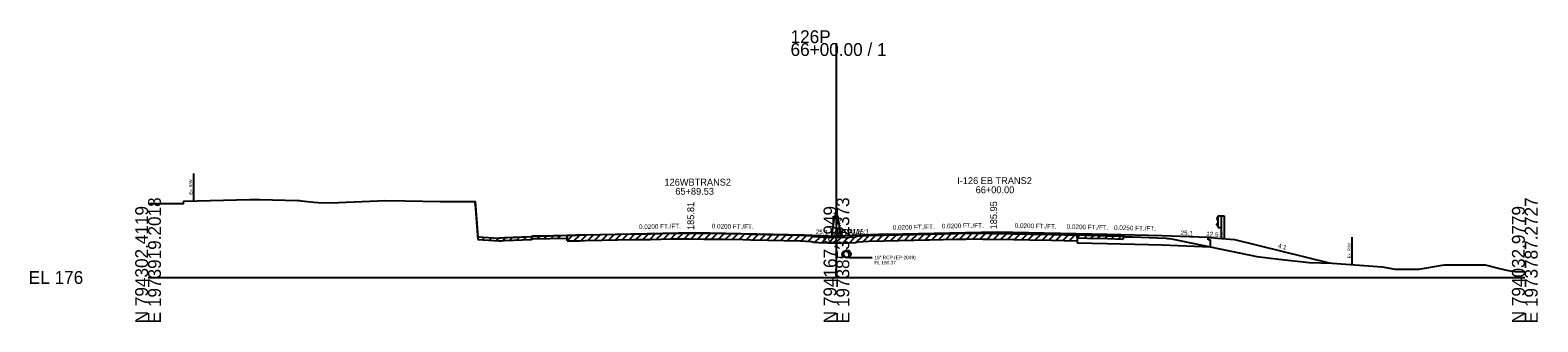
# Model space of a CAD drawing. Extents: x -161 to 1970889, y -4362 to 797231.
# Drawn here: x 2974.3 to 3302.8, y 1490.3 to 1554 of the extents above; entities that cross this region are included whole.
import ezdxf

# ---------------------------------------------------------------- set-up
doc = ezdxf.new("R2010")
doc.units = 0
for name, color, linetype in [('Default', 7, 'Continuous'), ('RD_GPK_XS_Cell', 7, 'Continuous'), ('RD_XS_Base', 7, 'Continuous'), ('RD_XS_EarthShd', 7, 'Continuous'), ('RD_XS_ExGround', 7, 'Continuous'), ('RD_XS_ExPaveRet', 7, 'Continuous'), ('RD_XS_ExRW', 7, 'Continuous'), ('RD_XS_GR', 7, 'Continuous'), ('RD_XS_MedBWall', 7, 'Continuous'), ('RD_XS_Misc_Line', 7, 'Continuous'), ('RD_XS_Pave', 7, 'Continuous'), ('RD_XS_PaveOvlay', 7, 'Continuous'), ('RD_XS_PaveShd', 7, 'Continuous'), ('RD_XS_Pipe', 7, 'Continuous'), ('RD_XS_TieSlope', 7, 'Continuous'), ('RD_XS_TX_Elev_EX', 7, 'Continuous'), ('RD_XS_TX_Elev_PR', 7, 'Continuous'), ('RD_XS_TX_MkPT', 7, 'Continuous'), ('RD_XS_TX_Profile', 7, 'Continuous'), ('RD_XS_TX_ShdSlope', 7, 'Continuous'), ('RD_XS_TX_Slope', 7, 'Continuous'), ('RD_XS_TX_Station', 7, 'Continuous')]:
    doc.layers.add(name, color=color, linetype=linetype)

msp = doc.modelspace()

# ---------------------------------------------------------------- linework, layer by layer
at = {"layer": 'RD_GPK_XS_Cell'}
for p, q in [((3150, 1500), (3150, 1551.16)), ((3000, 1500), (3150, 1500)), ((3150, 1500), (3300, 1500))]:
    msp.add_line(p, q, dxfattribs=at)
at = {"layer": 'RD_XS_Base'}
for p, q in [((3231.01, 1508.21), (3231.01, 1508.77)), ((3231.51, 1508.19), (3231.01, 1508.21)), ((3231.51, 1506.71), (3231.51, 1508.19)), ((3202.45, 1507.56), (3209, 1507.43)), ((3209, 1507.43), (3221, 1507.13)), ((3221, 1507.13), (3231.51, 1506.71))]:
    msp.add_line(p, q, dxfattribs=at)
at = {"layer": 'RD_XS_EarthShd'}
msp.add_line((3231.01, 1508.77), (3233.01, 1508.61), dxfattribs=at)
at = {"layer": 'RD_XS_ExGround'}
msp.add_lwpolyline([(3000, 1516.13), (3007.72, 1516.18), (3007.82, 1516.68), (3022.15, 1517), (3024.46, 1517.05), (3032.57, 1516.79), (3033.02, 1516.78), (3033.44, 1516.74), (3036.14, 1516.42), (3037.09, 1516.38), (3039.72, 1516.28), (3050.08, 1516.75), (3051.47, 1516.82), (3055.99, 1516.75), (3063.67, 1516.56), (3069.87, 1516.59), (3070.29, 1516.59), (3071.31, 1516.59), (3071.89, 1508.89), (3073.05, 1508.82), (3076.52, 1508.59), (3076.99, 1508.64), (3077.67, 1508.7), (3083.51, 1508.94), (3083.82, 1509.07), (3092.87, 1509.25), (3094.08, 1509.27), (3095.22, 1509.29), (3105.92, 1509.51), (3109.47, 1509.56), (3114.02, 1509.66), (3116.3, 1509.7), (3118.01, 1509.71), (3121.11, 1509.65), (3121.92, 1509.64), (3125.54, 1509.58), (3129.69, 1509.51), (3131.34, 1509.47), (3142.14, 1509.23), (3143.3, 1509.18), (3144.55, 1509.11), (3145.05, 1508.94), (3146.07, 1508.9), (3148.18, 1508.82), (3149.57, 1508.8), (3150, 1508.79), (3151.09, 1508.76), (3152.69, 1508.82), (3154.16, 1508.88), (3154.63, 1509.07), (3155.79, 1509.12), (3157.05, 1509.17), (3166.88, 1509.41), (3169.38, 1509.47), (3170.33, 1509.48), (3176.16, 1509.59), (3178.21, 1509.65), (3180.52, 1509.7), (3181.88, 1509.65), (3183.43, 1509.62), (3188.65, 1509.52), (3192.17, 1509.47), (3196.84, 1509.37), (3204.72, 1509.23), (3209.03, 1509.12), (3212.45, 1509.03), (3212.9, 1508.91), (3214.15, 1508.88), (3214.48, 1508.86), (3221.75, 1508.56), (3222.17, 1508.54), (3222.58, 1508.53), (3223.37, 1508.36), (3241.6, 1504.55), (3246.4, 1504.02), (3252.99, 1503.28), (3258.04, 1503.15), (3268.94, 1502.33), (3271.72, 1501.8), (3277, 1501.8), (3282.02, 1502.66), (3282.54, 1502.74), (3290.91, 1502.74), (3291.39, 1502.74), (3294.5, 1501.97), (3296.34, 1501.51), (3297.91, 1501.28), (3300, 1501.24)], dxfattribs=at)
at = {"layer": 'RD_XS_ExPaveRet'}
for p, q in [((3071.31, 1515.96), (3071.31, 1516.59)), ((3071.31, 1515.96), (3071.89, 1508.27)), ((3071.89, 1508.27), (3073.05, 1508.19)), ((3073.05, 1508.19), (3076.52, 1507.97)), ((3076.52, 1507.97), (3076.99, 1508.02)), ((3076.99, 1508.02), (3077.67, 1508.07)), ((3077.67, 1508.07), (3083.51, 1508.31)), ((3083.51, 1508.31), (3083.82, 1508.44)), ((3083.82, 1508.44), (3091.31, 1508.59)), ((3091.31, 1507.97), (3091.31, 1509.22)), ((3091.31, 1509.22), (3091.31, 1508.59)), ((3091.31, 1507.97), (3092.87, 1508)), ((3092.87, 1508), (3094.08, 1508.02)), ((3094.08, 1508.02), (3095.22, 1508.04)), ((3095.22, 1508.04), (3105.92, 1508.26)), ((3105.92, 1508.26), (3109.47, 1508.31)), ((3109.47, 1508.31), (3114.02, 1508.41)), ((3114.02, 1508.41), (3116.3, 1508.45)), ((3116.3, 1508.45), (3118.01, 1508.46)), ((3118.01, 1508.46), (3121.11, 1508.4)), ((3121.11, 1508.4), (3121.92, 1508.39)), ((3121.92, 1508.39), (3125.54, 1508.33)), ((3125.54, 1508.33), (3129.69, 1508.26)), ((3129.69, 1508.26), (3131.34, 1508.22)), ((3131.34, 1508.22), (3142.14, 1507.98)), ((3142.14, 1507.98), (3143.3, 1507.93)), ((3157.05, 1507.92), (3166.88, 1508.16)), ((3166.88, 1508.16), (3169.38, 1508.22)), ((3169.38, 1508.22), (3170.33, 1508.23)), ((3170.33, 1508.23), (3176.16, 1508.34)), ((3176.16, 1508.34), (3178.21, 1508.4)), ((3178.21, 1508.4), (3180.52, 1508.45)), ((3180.52, 1508.45), (3181.88, 1508.4)), ((3181.88, 1508.4), (3183.43, 1508.37)), ((3183.43, 1508.37), (3188.65, 1508.27)), ((3188.65, 1508.27), (3192.17, 1508.22)), ((3192.17, 1508.22), (3196.84, 1508.12)), ((3196.84, 1508.12), (3202.45, 1508.02)), ((3202.45, 1509.27), (3202.45, 1508.02)), ((3202.45, 1508.64), (3202.45, 1509.27)), ((3202.45, 1508.64), (3204.72, 1508.6)), ((3204.72, 1508.6), (3209.03, 1508.5)), ((3209.03, 1508.5), (3212.45, 1508.4)), ((3212.45, 1509.03), (3212.45, 1508.4)), ((3143.3, 1507.93), (3144.55, 1507.86)), ((3144.55, 1507.86), (3145.05, 1507.69)), ((3145.05, 1507.69), (3146.07, 1507.65)), ((3146.07, 1507.65), (3148.18, 1507.57)), ((3148.18, 1507.57), (3149.57, 1507.55)), ((3149.57, 1507.55), (3150, 1507.54)), ((3150, 1507.54), (3151.09, 1507.51)), ((3151.09, 1507.51), (3152.69, 1507.57)), ((3152.69, 1507.57), (3154.16, 1507.63)), ((3154.16, 1507.63), (3154.63, 1507.82)), ((3154.63, 1507.82), (3155.79, 1507.87)), ((3155.79, 1507.87), (3157.05, 1507.92))]:
    msp.add_line(p, q, dxfattribs=at)
at = {"layer": 'RD_XS_ExRW'}
for p, q in [((3009.88, 1522.73), (3009.88, 1516.73)), ((3262.31, 1508.83), (3262.31, 1502.83))]:
    msp.add_line(p, q, dxfattribs=at)
at = {"layer": 'RD_XS_GR'}
for p, q in [((3233.16, 1513.33), (3232.88, 1512.89)), ((3232.88, 1512.89), (3232.88, 1512.78)), ((3232.88, 1512.78), (3233.16, 1512.34)), ((3232.88, 1511.63), (3233.16, 1512.07)), ((3232.88, 1511.52), (3232.88, 1511.63)), ((3233.16, 1511.08), (3232.88, 1511.52)), ((3233.16, 1513.49), (3233.82, 1513.49)), ((3233.16, 1510.92), (3233.16, 1513.49)), ((3233.82, 1513.49), (3234.49, 1513.49)), ((3233.82, 1513.49), (3233.82, 1508.55)), ((3234.49, 1513.49), (3234.49, 1508.43)), ((3233.16, 1510.92), (3233.82, 1510.92))]:
    msp.add_line(p, q, dxfattribs=at)
at = {"layer": 'RD_XS_MedBWall'}
for p, q in [((3149, 1509.07), (3149.67, 1513.55)), ((3150.33, 1513.55), (3149.67, 1513.55)), ((3150.33, 1513.53), (3150.33, 1513.55)), ((3151, 1509.05), (3150.33, 1513.53))]:
    msp.add_line(p, q, dxfattribs=at)
at = {"layer": 'RD_XS_Misc_Line'}
for p, q in [((3071.31, 1515.96), (3071.35, 1516.01)), ((3072.81, 1508.21), (3073.39, 1508.79)), ((3074.31, 1508.11), (3074.9, 1508.7)), ((3075.81, 1508.01), (3076.4, 1508.6)), ((3077.31, 1508.04), (3077.97, 1508.71)), ((3078.81, 1508.12), (3079.46, 1508.77)), ((3080.31, 1508.18), (3080.96, 1508.83)), ((3081.81, 1508.24), (3082.46, 1508.89)), ((3083.31, 1508.3), (3084.08, 1509.07)), ((3084.81, 1508.46), (3085.45, 1509.1)), ((3086.31, 1508.49), (3086.95, 1509.13)), ((3087.81, 1508.52), (3088.45, 1509.16)), ((3089.31, 1508.55), (3089.95, 1509.19)), ((3091.31, 1507.97), (3092.58, 1509.24)), ((3092.81, 1508), (3094.08, 1509.27)), ((3094.31, 1508.02), (3095.58, 1509.3)), ((3095.81, 1508.05), (3097.08, 1509.33)), ((3097.31, 1508.08), (3098.58, 1509.36)), ((3098.81, 1508.11), (3100.08, 1509.39)), ((3100.31, 1508.14), (3101.58, 1509.42)), ((3101.81, 1508.17), (3103.08, 1509.45)), ((3103.31, 1508.2), (3104.58, 1509.48)), ((3104.81, 1508.23), (3106.08, 1509.51)), ((3106.31, 1508.26), (3107.58, 1509.53)), ((3107.81, 1508.29), (3109.08, 1509.55)), ((3109.31, 1508.31), (3110.58, 1509.58)), ((3110.81, 1508.34), (3112.09, 1509.62)), ((3112.31, 1508.37), (3113.59, 1509.65)), ((3113.81, 1508.4), (3115.08, 1509.68)), ((3115.31, 1508.43), (3116.58, 1509.7)), ((3116.81, 1508.45), (3118.07, 1509.71)), ((3118.31, 1508.46), (3119.53, 1509.68)), ((3119.81, 1508.43), (3121.03, 1509.66)), ((3121.31, 1508.4), (3122.54, 1509.63)), ((3122.81, 1508.38), (3124.04, 1509.61)), ((3124.31, 1508.35), (3125.54, 1509.58)), ((3125.81, 1508.33), (3127.04, 1509.55)), ((3127.31, 1508.3), (3128.54, 1509.53)), ((3128.81, 1508.27), (3130.04, 1509.5)), ((3130.31, 1508.25), (3131.53, 1509.47)), ((3131.81, 1508.21), (3133.03, 1509.44)), ((3133.31, 1508.18), (3134.53, 1509.4)), ((3134.81, 1508.15), (3136.03, 1509.37)), ((3136.31, 1508.11), (3137.53, 1509.33)), ((3137.81, 1508.08), (3139.03, 1509.3)), ((3139.31, 1508.04), (3140.53, 1509.27)), ((3140.81, 1508.01), (3142.03, 1509.23)), ((3142.31, 1507.97), (3143.5, 1509.17)), ((3143.81, 1507.9), (3144.9, 1508.99)), ((3145.31, 1507.68), (3146.51, 1508.88)), ((3146.81, 1507.62), (3148.01, 1508.83)), ((3148.31, 1507.57), (3149.54, 1508.8)), ((3149.81, 1507.54), (3151.03, 1508.76)), ((3151.31, 1507.52), (3152.61, 1508.82)), ((3152.81, 1507.58), (3154.1, 1508.87)), ((3154.31, 1507.69), (3155.74, 1509.12)), ((3155.81, 1507.87), (3157.11, 1509.17)), ((3157.31, 1507.93), (3158.59, 1509.21)), ((3158.81, 1507.96), (3160.09, 1509.24)), ((3160.31, 1508), (3161.59, 1509.28)), ((3161.81, 1508.03), (3163.09, 1509.31)), ((3163.31, 1508.07), (3164.59, 1509.35)), ((3164.81, 1508.11), (3166.09, 1509.39)), ((3166.31, 1508.14), (3167.59, 1509.42)), ((3167.81, 1508.18), (3169.09, 1509.46)), ((3169.31, 1508.21), (3170.58, 1509.49)), ((3170.81, 1508.24), (3172.08, 1509.52)), ((3172.31, 1508.27), (3173.58, 1509.54)), ((3173.81, 1508.3), (3175.08, 1509.57)), ((3175.31, 1508.33), (3176.58, 1509.61)), ((3176.81, 1508.36), (3178.09, 1509.64)), ((3178.31, 1508.4), (3179.59, 1509.68)), ((3179.81, 1508.43), (3181.06, 1509.68)), ((3181.31, 1508.42), (3182.53, 1509.64)), ((3182.81, 1508.38), (3184.03, 1509.61)), ((3184.31, 1508.35), (3185.53, 1509.58)), ((3185.81, 1508.33), (3187.03, 1509.55)), ((3187.31, 1508.3), (3188.53, 1509.52)), ((3188.81, 1508.27), (3190.04, 1509.5)), ((3190.31, 1508.25), (3191.54, 1509.48)), ((3191.81, 1508.22), (3193.03, 1509.45)), ((3193.31, 1508.19), (3194.53, 1509.42)), ((3194.81, 1508.16), (3196.03, 1509.39)), ((3196.31, 1508.13), (3197.53, 1509.36)), ((3197.81, 1508.1), (3199.04, 1509.33)), ((3199.31, 1508.08), (3200.54, 1509.3)), ((3200.81, 1508.05), (3202.04, 1509.28)), ((3202.45, 1508.64), (3203.06, 1509.26)), ((3203.95, 1508.62), (3204.56, 1509.23)), ((3205.45, 1508.58), (3206.06, 1509.19)), ((3206.95, 1508.55), (3207.56, 1509.16)), ((3208.45, 1508.51), (3209.06, 1509.12)), ((3209.95, 1508.47), (3210.55, 1509.08)), ((3211.45, 1508.43), (3212.05, 1509.04))]:
    msp.add_line(p, q, dxfattribs=at)
at = {"layer": 'RD_XS_Pave'}
for p, q in [((3095, 1509.33), (3119, 1509.81)), ((3119, 1509.81), (3143, 1509.33)), ((3161, 1509.47), (3185, 1509.95)), ((3185, 1509.95), (3209, 1509.47)), ((3209, 1509.47), (3221, 1509.17))]:
    msp.add_line(p, q, dxfattribs=at)
at = {"layer": 'RD_XS_PaveOvlay'}
for p, q in [((3150, 1508.79), (3151.09, 1508.76)), ((3151.09, 1508.76), (3152.69, 1508.82)), ((3152.69, 1508.82), (3154.16, 1508.88)), ((3154.16, 1508.88), (3154.63, 1509.07)), ((3154.63, 1509.07), (3155.79, 1509.12)), ((3155.79, 1509.12), (3157.05, 1509.17)), ((3157.05, 1509.17), (3166.88, 1509.41)), ((3166.88, 1509.41), (3169.38, 1509.47)), ((3169.38, 1509.47), (3170.33, 1509.48)), ((3170.33, 1509.48), (3176.16, 1509.59)), ((3176.16, 1509.59), (3178.21, 1509.65)), ((3178.21, 1509.65), (3180.52, 1509.7)), ((3180.52, 1509.7), (3181.88, 1509.65)), ((3181.88, 1509.65), (3183.43, 1509.62)), ((3183.43, 1509.62), (3188.65, 1509.52)), ((3188.65, 1509.52), (3192.17, 1509.47)), ((3192.17, 1509.47), (3196.84, 1509.37)), ((3196.84, 1509.37), (3202.45, 1509.27)), ((3202.45, 1509.27), (3202.45, 1507.56))]:
    msp.add_line(p, q, dxfattribs=at)
at = {"layer": 'RD_XS_PaveShd'}
for p, q in [((3095, 1509.33), (3076.52, 1508.59)), ((3143, 1509.33), (3150, 1509.05)), ((3161, 1509.47), (3150, 1509.03)), ((3221, 1509.17), (3231.01, 1508.77))]:
    msp.add_line(p, q, dxfattribs=at)
at = {"layer": 'RD_XS_Pipe'}
msp.add_line((3152.78, 1504.37), (3157.78, 1504.37), dxfattribs=at)
for radius in [0.85, 0.75]:
    msp.add_circle((3152.28, 1505.12), radius, dxfattribs=at)
at = {"layer": 'RD_XS_TieSlope'}
for p, q in [((3233.01, 1508.61), (3236.76, 1508.32)), ((3236.76, 1508.32), (3257.38, 1503.17))]:
    msp.add_line(p, q, dxfattribs=at)

# ---------------------------------------------------------------- texts
at = {"layer": 'Default'}
for p in [(3150, 1509.05), (3150, 1508.94)]:
    msp.add_text('35', height=1.5, dxfattribs=at).set_placement(p)
at = {"layer": 'RD_GPK_XS_Cell'}
for s, p in [('126P', (3140, 1551.16)), ('66+00.00 / 1', (3140, 1548.36)), ('EL 176', (2974, 1498.6))]:
    msp.add_text(s, height=2.8, dxfattribs=at).set_placement(p)
for s, p in [('N 794302.4119', (3000, 1490)), ('E 1973919.2018', (3002.8, 1490)), ('N 794167.6949', (3150, 1490)), ('E 1973853.2373', (3152.8, 1490)), ('N 794032.9779', (3300, 1490)), ('E 1973787.2727', (3302.8, 1490))]:
    msp.add_text(s, height=2.8, rotation=90, dxfattribs=at).set_placement(p)
at = {"layer": 'RD_XS_ExRW'}
for p in [(3009.63, 1518.11), (3262.06, 1504.21)]:
    msp.add_text('Ex. R/W ', height=0.65, rotation=90, dxfattribs=at).set_placement(p)
at = {"layer": 'RD_XS_Pipe'}
for s, p in [('18" RCP (EP-2049)', (3158.28, 1503.99)), ('FL 180.37', (3158.28, 1502.87))]:
    msp.add_text(s, height=0.75, dxfattribs=at).set_placement(p)
at = {"layer": 'RD_XS_TX_Elev_EX'}
msp.add_text('184.79', height=1, rotation=90, dxfattribs=at).set_placement((3151, 1508.79))
at = {"layer": 'RD_XS_TX_Elev_PR'}
for s, p in [(' 185.81', (3119, 1509.81)), (' 185.95', (3185, 1509.95))]:
    msp.add_text(s, height=1.5, rotation=90, dxfattribs=at).set_placement(p)
at = {"layer": 'RD_XS_TX_MkPT'}
for s, p in [('WBW', (3149, 1509.07)), ('EBW', (3151, 1509.05))]:
    msp.add_text(s, height=1.5, dxfattribs=at).set_placement(p)
at = {"layer": 'RD_XS_TX_Profile'}
for rotation, p in [(357.7094, (3145.46, 1509.48)), (2.2906, (3154.44, 1509.46)), (357.7112, (3224.96, 1509.26))]:
    msp.add_text('25:1', height=1, rotation=rotation, dxfattribs=at).set_placement(p)
at = {"layer": 'RD_XS_TX_ShdSlope'}
msp.add_text('12.5:1', height=1, rotation=355.4297, dxfattribs=at).set_placement((3230.55, 1509.06))
at = {"layer": 'RD_XS_TX_Slope'}
for s, rotation, p in [('0.0200 FT./FT.', 1.1458, (3106.98, 1510.57)), ('0.0200 FT./FT.', 358.8542, (3122.83, 1510.73)), ('0.0200 FT./FT.', 1.1458, (3162.3, 1510.39)), ('0.0200 FT./FT.', 1.1458, (3172.98, 1510.71)), ('0.0200 FT./FT.', 358.569, (3188.84, 1510.86)), ('0.0200 FT./FT.', 358.5681, (3200.15, 1510.63)), ('0.0250 FT./FT.', 358.569, (3210.47, 1510.4)), ('4:1', 345.9745, (3246.11, 1506.5))]:
    msp.add_text(s, height=1, rotation=rotation, dxfattribs=at).set_placement(p)
at = {"layer": 'RD_XS_TX_Station'}
for s, p in [('126WBTRANS2', (3112.53, 1520.06)), ('I-126 EB TRANS2', (3176.31, 1520.39)), ('65+89.53', (3114.89, 1518.06)), ('66+00.00', (3180.33, 1518.39))]:
    msp.add_text(s, height=1.5, dxfattribs=at).set_placement(p)

doc.saveas('drawing.dxf')
